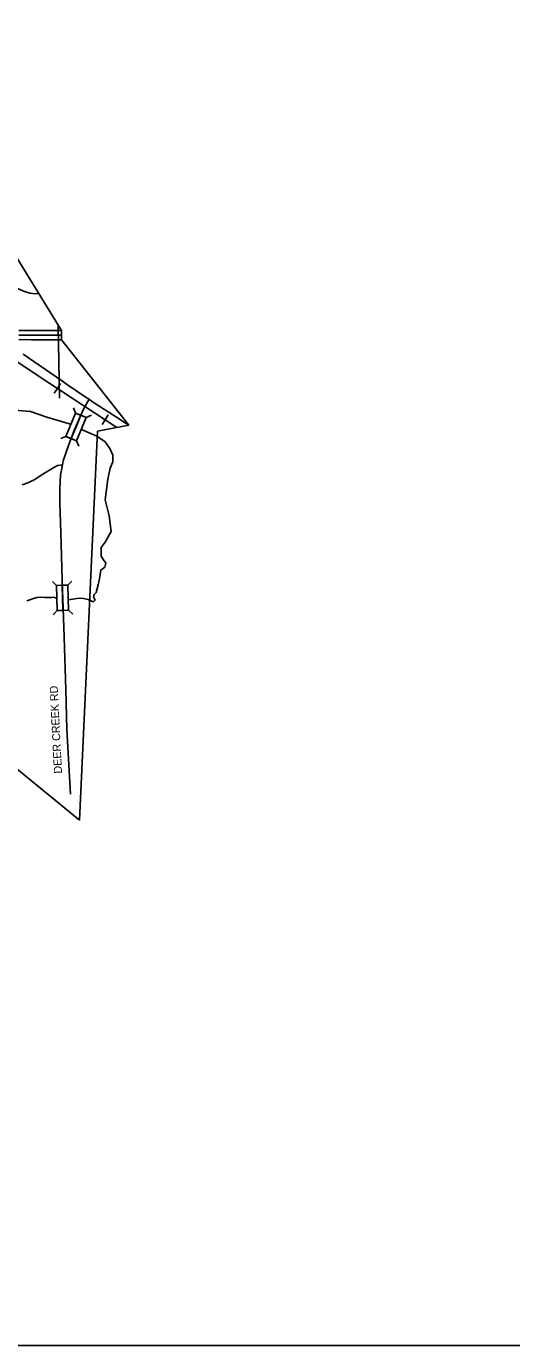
# Model space of a CAD drawing. Extents: x 281.94 to 289.14, y 116.09 to 120.89.
# Drawn here: x 286.65 to 287.499, y 116.187 to 118.495 of the extents above; entities that cross this region are included whole.
import ezdxf

# ---------------------------------------------------------------- set-up
doc = ezdxf.new("R2010")
doc.units = 0
for name, color, linetype in [('tdCiAdjCityStreetCL', 7, 'Continuous'), ('tdCiHydroRiver', 7, 'Continuous'), ('tdCiInt', 7, 'Continuous'), ('tdCiIntCL', 7, 'Continuous'), ('tdCiMapFrame', 7, 'Continuous'), ('tdCiMapPltShpe', 7, 'Continuous'), ('tdCiPriCL', 7, 'Continuous'), ('tdCiPriDiv', 7, 'Continuous'), ('tdCiRRCL', 7, 'Continuous'), ('tdCiSecCL', 7, 'Continuous'), ('tdCiSecText', 7, 'Continuous'), ('tdCiSectLine', 7, 'Continuous'), ('tdCiStrucDataSec', 7, 'Continuous')]:
    doc.layers.add(name, color=color, linetype=linetype)

msp = doc.modelspace()

# ---------------------------------------------------------------- linework, layer by layer
at = {"layer": 'tdCiAdjCityStreetCL'}
for points in [[(286.4129, 118.2404), (286.4205, 118.2351), (286.4722, 118.1967), (286.5036, 118.1723), (286.5374, 118.1461), (286.5613, 118.1261), (286.5667, 118.1212), (286.5753, 118.1128), (286.5869, 118.0997), (286.5941, 118.0909), (286.6039, 118.0741), (286.6126, 118.0591), (286.6182, 118.0509), (286.6242, 118.0452), (286.6284, 118.0413), (286.635, 118.0369), (286.6412, 118.0339), (286.6486, 118.0309), (286.6562, 118.0285), (286.6663, 118.0275), (286.672, 118.0276)], [(286.6429, 117.6933), (286.6528, 117.6965), (286.6639, 117.7019), (286.6792, 117.7115), (286.6982, 117.7236), (286.7048, 117.727), (286.7134, 117.728), (286.7146, 117.735), (286.7244, 117.7634), (286.7304, 117.7788), (286.7345, 117.7896), (286.7357, 117.7924), (286.7415, 117.8057), (286.7429, 117.8084), (286.75, 117.8252), (286.7601, 117.8431)]]:
    msp.add_lwpolyline(points, dxfattribs=at)
at = {"layer": 'tdCiHydroRiver'}
for points in [[(286.6237, 117.8242), (286.6574, 117.8214), (286.686, 117.8113), (286.7276, 117.7991)], [(286.7241, 117.4921), (286.742, 117.4947), (286.75, 117.4942), (286.7581, 117.4925), (286.7677, 117.4884), (286.7706, 117.4915), (286.7678, 117.4969), (286.7686, 117.5013), (286.7724, 117.5046), (286.7757, 117.518), (286.7784, 117.5284), (286.7805, 117.5439), (286.7876, 117.549), (286.7894, 117.5558), (286.7838, 117.5633), (286.7811, 117.5681), (286.7814, 117.5836), (286.7882, 117.5928), (286.7989, 117.6116), (286.7951, 117.639), (286.7884, 117.667), (286.7926, 117.7028), (286.7968, 117.7225), (286.8015, 117.7335), (286.8018, 117.7448), (286.7962, 117.7564), (286.7884, 117.7683), (286.7738, 117.7785), (286.747, 117.7898)], [(286.6514, 117.4898), (286.6561, 117.4916), (286.6626, 117.494), (286.6686, 117.4961), (286.6747, 117.4962), (286.6827, 117.4959), (286.6946, 117.4957), (286.6985, 117.4966), (286.7035, 117.494)]]:
    msp.add_lwpolyline(points, dxfattribs=at)
at = {"layer": 'tdCiInt'}
for points in [[(286.6373, 117.9632), (286.6587, 117.9629), (286.7039, 117.9629), (286.7118, 117.963)], [(286.6373, 117.9472), (286.6586, 117.9469), (286.704, 117.9469), (286.7119, 117.947)]]:
    msp.add_lwpolyline(points, dxfattribs=at)
at = {"layer": 'tdCiIntCL'}
msp.add_lwpolyline([(286.6373, 117.9552), (286.6587, 117.9549), (286.704, 117.9549), (286.7119, 117.955)], dxfattribs=at)
at = {"layer": 'tdCiMapFrame'}
msp.add_lwpolyline([(289.038, 120.7868), (289.038, 116.1868), (282.038, 116.1868), (282.038, 120.7868), (289.038, 120.7868)], dxfattribs=at)
at = {"layer": 'tdCiMapPltShpe'}
msp.add_line((286.7431, 117.1063), (286.775, 117.7868), dxfattribs=at)
for points in [[(286.7119, 117.9469), (286.7118, 117.9629), (285.5135, 119.9142)], [(286.775, 117.7868), (286.8293, 117.7976), (286.7119, 117.9469)], [(285.8966, 117.3851), (286.4365, 117.3571), (286.7431, 117.1063)]]:
    msp.add_lwpolyline(points, dxfattribs=at)
at = {"layer": 'tdCiPriCL'}
msp.add_lwpolyline([(286.6445, 117.9215), (286.7118, 117.8754), (286.7224, 117.8681), (286.7585, 117.8435), (286.7601, 117.8431), (286.7644, 117.8395), (286.8015, 117.8156), (286.8144, 117.8072), (286.8219, 117.8024), (286.8293, 117.7976)], dxfattribs=at)
at = {"layer": 'tdCiPriDiv'}
msp.add_lwpolyline([(286.6445, 117.9215), (286.7118, 117.8754), (286.7224, 117.8681), (286.7585, 117.8435), (286.7601, 117.8431), (286.7644, 117.8395), (286.8015, 117.8156), (286.8144, 117.8072), (286.8219, 117.8024), (286.8293, 117.7976)], dxfattribs=at)
at = {"layer": 'tdCiRRCL'}
for points in [[(286.594, 117.9344), (286.6562, 117.8935), (286.6712, 117.8836), (286.8085, 117.7935)], [(286.594, 117.9344), (286.6562, 117.8935), (286.6712, 117.8836), (286.8085, 117.7935)], [(286.699, 117.8534), (286.7045, 117.8617), (286.71, 117.8701)], [(286.7826, 117.7985), (286.7881, 117.8069), (286.7936, 117.8153)]]:
    msp.add_lwpolyline(points, dxfattribs=at)
at = {"layer": 'tdCiSecCL'}
msp.add_lwpolyline([(286.7272, 117.1517), (286.7213, 117.2648), (286.7194, 117.3345), (286.7162, 117.4266), (286.7138, 117.4939), (286.7138, 117.496), (286.7135, 117.5052), (286.7134, 117.5069), (286.7105, 117.6089), (286.7086, 117.6622), (286.7086, 117.6871), (286.7102, 117.7098), (286.7134, 117.728)], dxfattribs=at)
at = {"layer": 'tdCiSectLine'}
msp.add_line((286.7062, 117.9719), (286.7084, 117.845), dxfattribs=at)
at = {"layer": 'tdCiStrucDataSec'}
for points in [[(286.7548, 117.8109), (286.7456, 117.8147), (286.7364, 117.8185), (286.7325, 117.8278)], [(286.7364, 117.8185), (286.7195, 117.7779), (286.7103, 117.774)], [(286.7288, 117.774), (286.7372, 117.7944), (286.7456, 117.8147)], [(286.738, 117.7702), (286.7548, 117.8109), (286.7641, 117.8147)], [(286.7195, 117.7779), (286.7288, 117.774), (286.738, 117.7702), (286.7418, 117.761)], [(286.723, 117.5175), (286.713, 117.5172), (286.703, 117.517), (286.6958, 117.5239)], [(286.703, 117.517), (286.7041, 117.473), (286.6972, 117.4657)], [(286.7141, 117.4732), (286.7135, 117.4952), (286.713, 117.5172)], [(286.7241, 117.4735), (286.723, 117.5175), (286.7299, 117.5247)], [(286.7041, 117.473), (286.7141, 117.4732), (286.7241, 117.4735), (286.7313, 117.4666)]]:
    msp.add_lwpolyline(points, dxfattribs=at)
for points in [[(286.7195, 117.7779), (286.7364, 117.8185), (286.7548, 117.8109), (286.738, 117.7702)], [(286.7041, 117.473), (286.703, 117.517), (286.723, 117.5175), (286.7241, 117.4735)]]:
    msp.add_lwpolyline(points, close=True, dxfattribs=at)

# ---------------------------------------------------------------- texts
at = {"layer": 'tdCiSecText'}
msp.add_text('DEER CREEK RD', height=0.014, rotation=92.8894, dxfattribs=at).set_placement((286.7127, 117.1881))

doc.saveas('drawing.dxf')
